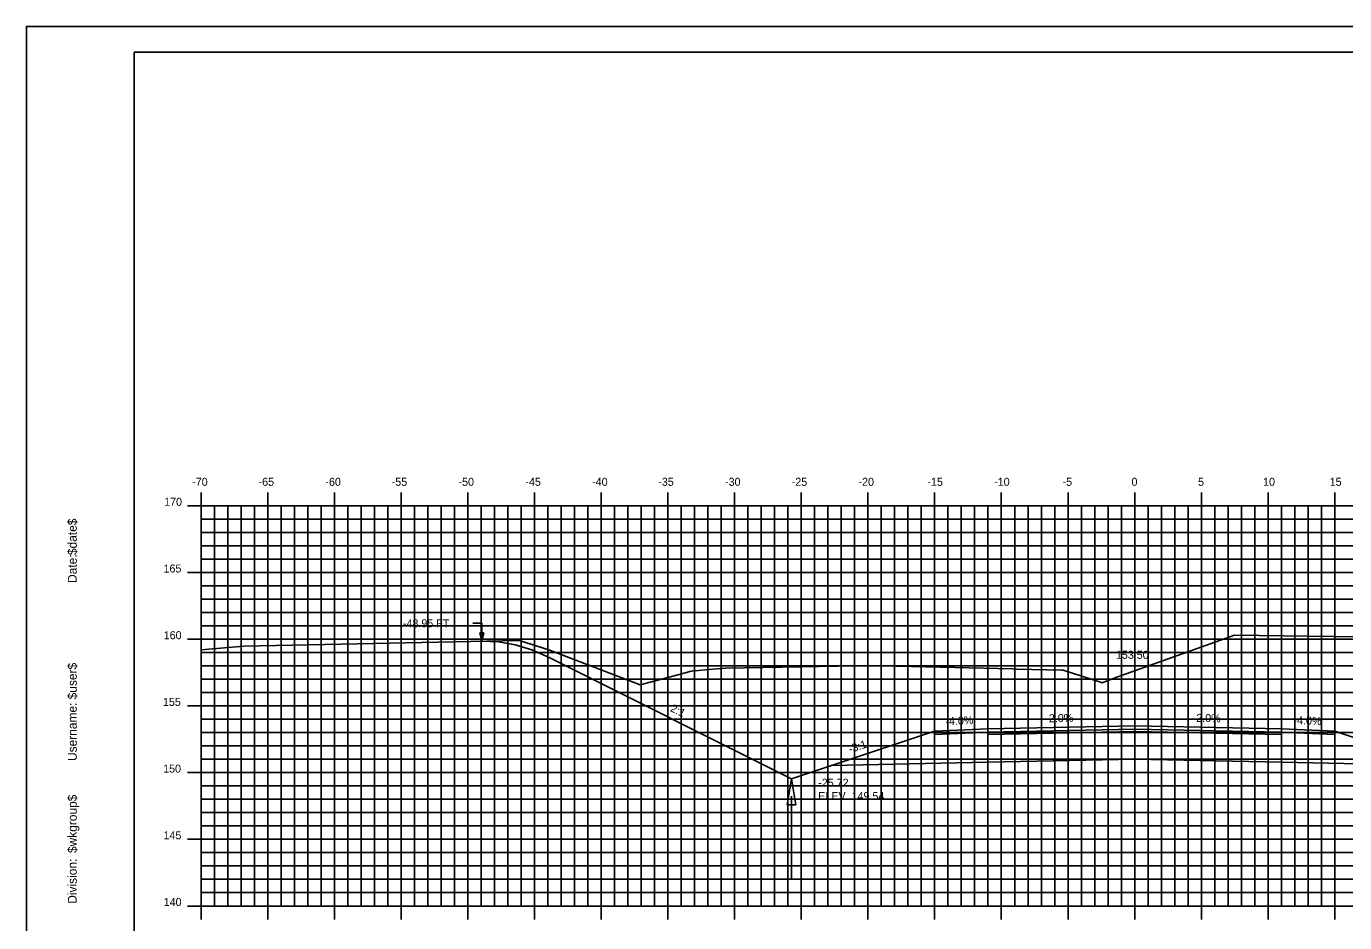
# Model space of a CAD drawing. Extents: x 1143420 to 1143590, y 608981 to 609091.
# Drawn here: x 1143420 to 1143518.8, y 609024.1 to 609091.3 of the extents above; entities that cross this region are included whole.
import ezdxf

# ---------------------------------------------------------------- set-up
doc = ezdxf.new("R2010")
doc.units = 0
for name, color, linetype in [('ANNOTATION', 7, 'Continuous'), ('BORDER', 7, 'Continuous'), ('D_Drainage_Ditch_Line', 7, 'Continuous'), ('D_Roadway_Centerline', 7, 'Continuous'), ('D_Roadway_Centerline_Text', 7, 'Continuous'), ('D_Roadway_Edge_Shoulder', 7, 'Continuous'), ('D_Roadway_Edge_TW', 7, 'Continuous'), ('D_Roadway_Pavement', 7, 'Continuous'), ('D_Roadway_SlopeLines', 7, 'Continuous'), ('D_Roadway_SubGrade', 7, 'Continuous'), ('D_Text_Standard', 7, 'Continuous'), ('H_V ANNOTATION', 7, 'Continuous'), ('MAJOR', 7, 'Continuous'), ('MINOR', 7, 'Continuous'), ('PLOT BOUNDARY', 7, 'Continuous'), ('S_Roadway_Centerline', 7, 'Continuous')]:
    doc.layers.add(name, color=color, linetype=linetype)

msp = doc.modelspace()

# ---------------------------------------------------------------- linework, layer by layer
msp.add_lwpolyline([(1143454.133, 609045.188), (1143455.383, 609045.133), (1143456.633, 609044.915), (1143457.883, 609044.534), (1143459.133, 609043.99), (1143477.355, 609034.879), (1143480.355, 609035.879), (1143488.079, 609038.454), (1143488.08, 609038.454), (1143492.08, 609038.614), (1143503.08, 609038.834), (1143514.08, 609038.614), (1143518.08, 609038.454), (1143525.803, 609035.879), (1143528.803, 609034.879), (1143546.922, 609043.939), (1143548.172, 609044.484), (1143549.422, 609044.87), (1143550.672, 609045.096), (1143551.922, 609045.163)])
at = {"layer": 'BORDER'}
msp.add_lwpolyline([(1143428.08, 608984.335), (1143588.08, 608984.335), (1143588.08, 609089.335), (1143428.08, 609089.335)], close=True, dxfattribs=at)
at = {"layer": 'D_Drainage_Ditch_Line'}
msp.add_line((1143477.355, 609033.567), (1143477.355, 609027.323), dxfattribs=at)
msp.add_lwpolyline([(1143477.683, 609032.911), (1143477.027, 609032.911), (1143477.355, 609034.879)], close=True, dxfattribs=at)
at = {"layer": 'D_Roadway_Edge_Shoulder'}
for points in [[(1143492.08, 609038.614), (1143488.08, 609038.454), (1143488.08, 609038.204), (1143492.08, 609038.364)], [(1143514.08, 609038.614), (1143518.08, 609038.454), (1143518.08, 609038.204), (1143514.08, 609038.364)]]:
    msp.add_lwpolyline(points, close=True, dxfattribs=at)
at = {"layer": 'D_Roadway_Edge_TW'}
msp.add_lwpolyline([(1143492.08, 609038.364), (1143492.08, 609038.614), (1143503.08, 609038.834), (1143514.08, 609038.614), (1143514.08, 609038.364), (1143503.08, 609038.584)], close=True, dxfattribs=at)
at = {"layer": 'D_Roadway_Pavement'}
msp.add_lwpolyline([(1143492.08, 609038.197), (1143492.08, 609038.364), (1143503.08, 609038.584), (1143514.08, 609038.364), (1143514.08, 609038.197), (1143503.08, 609038.417)], close=True, dxfattribs=at)
at = {"layer": 'D_Roadway_SlopeLines'}
for points in [[(1143477.355, 609034.879), (1143459.133, 609043.99), (1143457.883, 609044.534), (1143456.633, 609044.915), (1143455.383, 609045.133), (1143454.133, 609045.188)], [(1143480.355, 609035.879), (1143477.355, 609034.879)]]:
    msp.add_lwpolyline(points, dxfattribs=at)
at = {"layer": 'D_Roadway_SubGrade'}
for points in [[(1143492.08, 609038.197), (1143492.08, 609038.364), (1143488.08, 609038.204), (1143488.08, 609038.454), (1143488.079, 609038.454), (1143480.355, 609035.879), (1143492.08, 609036.114)], [(1143492.08, 609036.114), (1143492.08, 609038.197), (1143503.08, 609038.417), (1143514.08, 609038.197), (1143514.08, 609036.114), (1143503.08, 609036.334)], [(1143514.08, 609038.197), (1143514.08, 609038.364), (1143518.08, 609038.204), (1143518.08, 609038.454), (1143518.08, 609038.454), (1143525.803, 609035.879), (1143514.08, 609036.114)]]:
    msp.add_lwpolyline(points, close=True, dxfattribs=at)
at = {"layer": 'D_Text_Standard'}
msp.add_lwpolyline([(1143454.133, 609045.24), (1143454.129, 609046.527), (1143453.449, 609046.527)], dxfattribs=at)
msp.add_lwpolyline([(1143454.133, 609045.24), (1143453.986, 609045.822), (1143454.277, 609045.823)], close=True, dxfattribs=at)
at = {"layer": 'MAJOR'}
for p, q in [((1143433.08, 609056.337), (1143433.08, 609055.335)), ((1143438.08, 609056.337), (1143438.08, 609055.335)), ((1143443.08, 609056.337), (1143443.08, 609055.335)), ((1143448.08, 609056.337), (1143448.08, 609055.335)), ((1143453.08, 609056.337), (1143453.08, 609055.335)), ((1143458.08, 609056.337), (1143458.08, 609055.335)), ((1143463.08, 609056.337), (1143463.08, 609055.335)), ((1143468.08, 609056.337), (1143468.08, 609055.335)), ((1143473.08, 609056.337), (1143473.08, 609055.335)), ((1143478.08, 609056.337), (1143478.08, 609055.335)), ((1143483.08, 609056.337), (1143483.08, 609055.335)), ((1143488.08, 609056.337), (1143488.08, 609055.335)), ((1143493.08, 609056.337), (1143493.08, 609055.335)), ((1143498.08, 609056.337), (1143498.08, 609055.335)), ((1143503.08, 609056.337), (1143503.08, 609055.335)), ((1143508.08, 609056.337), (1143508.08, 609055.335)), ((1143513.08, 609056.337), (1143513.08, 609055.335)), ((1143518.08, 609056.337), (1143518.08, 609055.335)), ((1143432.078, 609055.335), (1143433.08, 609055.335)), ((1143433.08, 609055.335), (1143573.08, 609055.335)), ((1143433.08, 609025.335), (1143433.08, 609055.335)), ((1143433.08, 609025.335), (1143433.08, 609055.335)), ((1143433.08, 609055.335), (1143573.08, 609055.335)), ((1143438.08, 609025.335), (1143438.08, 609055.335)), ((1143443.08, 609025.335), (1143443.08, 609055.335)), ((1143448.08, 609025.335), (1143448.08, 609055.335)), ((1143453.08, 609025.335), (1143453.08, 609055.335)), ((1143458.08, 609025.335), (1143458.08, 609055.335)), ((1143463.08, 609025.335), (1143463.08, 609055.335)), ((1143468.08, 609025.335), (1143468.08, 609055.335)), ((1143473.08, 609025.335), (1143473.08, 609055.335)), ((1143478.08, 609025.335), (1143478.08, 609055.335)), ((1143483.08, 609025.335), (1143483.08, 609055.335)), ((1143488.08, 609025.335), (1143488.08, 609055.335)), ((1143493.08, 609025.335), (1143493.08, 609055.335)), ((1143498.08, 609025.335), (1143498.08, 609055.335)), ((1143503.08, 609025.335), (1143503.08, 609055.335)), ((1143508.08, 609025.335), (1143508.08, 609055.335)), ((1143513.08, 609025.335), (1143513.08, 609055.335)), ((1143518.08, 609025.335), (1143518.08, 609055.335)), ((1143432.078, 609050.335), (1143433.08, 609050.335)), ((1143433.08, 609050.335), (1143573.08, 609050.335)), ((1143432.078, 609045.335), (1143433.08, 609045.335)), ((1143433.08, 609045.335), (1143573.08, 609045.335)), ((1143432.078, 609040.335), (1143433.08, 609040.335)), ((1143433.08, 609040.335), (1143573.08, 609040.335)), ((1143432.078, 609035.335), (1143433.08, 609035.335)), ((1143433.08, 609035.335), (1143573.08, 609035.335)), ((1143432.078, 609030.335), (1143433.08, 609030.335)), ((1143433.08, 609030.335), (1143573.08, 609030.335)), ((1143432.078, 609025.335), (1143433.08, 609025.335)), ((1143433.08, 609025.335), (1143573.08, 609025.335)), ((1143433.08, 609025.335), (1143573.08, 609025.335)), ((1143433.08, 609024.333), (1143433.08, 609025.335)), ((1143438.08, 609024.333), (1143438.08, 609025.335)), ((1143443.08, 609024.333), (1143443.08, 609025.335)), ((1143448.08, 609024.333), (1143448.08, 609025.335)), ((1143453.08, 609024.333), (1143453.08, 609025.335)), ((1143458.08, 609024.333), (1143458.08, 609025.335)), ((1143463.08, 609024.333), (1143463.08, 609025.335)), ((1143468.08, 609024.333), (1143468.08, 609025.335)), ((1143473.08, 609024.333), (1143473.08, 609025.335)), ((1143478.08, 609024.333), (1143478.08, 609025.335)), ((1143483.08, 609024.333), (1143483.08, 609025.335)), ((1143488.08, 609024.333), (1143488.08, 609025.335)), ((1143493.08, 609024.333), (1143493.08, 609025.335)), ((1143498.08, 609024.333), (1143498.08, 609025.335)), ((1143503.08, 609024.333), (1143503.08, 609025.335)), ((1143508.08, 609024.333), (1143508.08, 609025.335)), ((1143513.08, 609024.333), (1143513.08, 609025.335)), ((1143518.08, 609024.333), (1143518.08, 609025.335))]:
    msp.add_line(p, q, dxfattribs=at)
at = {"layer": 'MINOR'}
for p, q in [((1143434.08, 609025.335), (1143434.08, 609055.335)), ((1143435.08, 609025.335), (1143435.08, 609055.335)), ((1143436.08, 609025.335), (1143436.08, 609055.335)), ((1143437.08, 609025.335), (1143437.08, 609055.335)), ((1143439.08, 609025.335), (1143439.08, 609055.335)), ((1143440.08, 609025.335), (1143440.08, 609055.335)), ((1143441.08, 609025.335), (1143441.08, 609055.335)), ((1143442.08, 609025.335), (1143442.08, 609055.335)), ((1143444.08, 609025.335), (1143444.08, 609055.335)), ((1143445.08, 609025.335), (1143445.08, 609055.335)), ((1143446.08, 609025.335), (1143446.08, 609055.335)), ((1143447.08, 609025.335), (1143447.08, 609055.335)), ((1143449.08, 609025.335), (1143449.08, 609055.335)), ((1143450.08, 609025.335), (1143450.08, 609055.335)), ((1143451.08, 609025.335), (1143451.08, 609055.335)), ((1143452.08, 609025.335), (1143452.08, 609055.335)), ((1143454.08, 609025.335), (1143454.08, 609055.335)), ((1143455.08, 609025.335), (1143455.08, 609055.335)), ((1143456.08, 609025.335), (1143456.08, 609055.335)), ((1143457.08, 609025.335), (1143457.08, 609055.335)), ((1143459.08, 609025.335), (1143459.08, 609055.335)), ((1143460.08, 609025.335), (1143460.08, 609055.335)), ((1143461.08, 609025.335), (1143461.08, 609055.335)), ((1143462.08, 609025.335), (1143462.08, 609055.335)), ((1143464.08, 609025.335), (1143464.08, 609055.335)), ((1143465.08, 609025.335), (1143465.08, 609055.335)), ((1143466.08, 609025.335), (1143466.08, 609055.335)), ((1143467.08, 609025.335), (1143467.08, 609055.335)), ((1143469.08, 609025.335), (1143469.08, 609055.335)), ((1143470.08, 609025.335), (1143470.08, 609055.335)), ((1143471.08, 609025.335), (1143471.08, 609055.335)), ((1143472.08, 609025.335), (1143472.08, 609055.335)), ((1143474.08, 609025.335), (1143474.08, 609055.335)), ((1143475.08, 609025.335), (1143475.08, 609055.335)), ((1143476.08, 609025.335), (1143476.08, 609055.335)), ((1143477.08, 609025.335), (1143477.08, 609055.335)), ((1143479.08, 609025.335), (1143479.08, 609055.335)), ((1143480.08, 609025.335), (1143480.08, 609055.335)), ((1143481.08, 609025.335), (1143481.08, 609055.335)), ((1143482.08, 609025.335), (1143482.08, 609055.335)), ((1143484.08, 609025.335), (1143484.08, 609055.335)), ((1143485.08, 609025.335), (1143485.08, 609055.335)), ((1143486.08, 609025.335), (1143486.08, 609055.335)), ((1143487.08, 609025.335), (1143487.08, 609055.335)), ((1143489.08, 609025.335), (1143489.08, 609055.335)), ((1143490.08, 609025.335), (1143490.08, 609055.335)), ((1143491.08, 609025.335), (1143491.08, 609055.335)), ((1143492.08, 609025.335), (1143492.08, 609055.335)), ((1143494.08, 609025.335), (1143494.08, 609055.335)), ((1143495.08, 609025.335), (1143495.08, 609055.335)), ((1143496.08, 609025.335), (1143496.08, 609055.335)), ((1143497.08, 609025.335), (1143497.08, 609055.335)), ((1143499.08, 609025.335), (1143499.08, 609055.335)), ((1143500.08, 609025.335), (1143500.08, 609055.335)), ((1143501.08, 609025.335), (1143501.08, 609055.335)), ((1143502.08, 609025.335), (1143502.08, 609055.335)), ((1143504.08, 609025.335), (1143504.08, 609055.335)), ((1143505.08, 609025.335), (1143505.08, 609055.335)), ((1143506.08, 609025.335), (1143506.08, 609055.335)), ((1143507.08, 609025.335), (1143507.08, 609055.335)), ((1143509.08, 609025.335), (1143509.08, 609055.335)), ((1143510.08, 609025.335), (1143510.08, 609055.335)), ((1143511.08, 609025.335), (1143511.08, 609055.335)), ((1143512.08, 609025.335), (1143512.08, 609055.335)), ((1143514.08, 609025.335), (1143514.08, 609055.335)), ((1143515.08, 609025.335), (1143515.08, 609055.335)), ((1143516.08, 609025.335), (1143516.08, 609055.335)), ((1143517.08, 609025.335), (1143517.08, 609055.335)), ((1143433.08, 609054.335), (1143573.08, 609054.335)), ((1143433.08, 609054.335), (1143434.082, 609054.335)), ((1143433.08, 609053.335), (1143573.08, 609053.335)), ((1143433.08, 609053.335), (1143434.082, 609053.335)), ((1143433.08, 609052.335), (1143573.08, 609052.335)), ((1143433.08, 609052.335), (1143434.082, 609052.335)), ((1143433.08, 609051.335), (1143573.08, 609051.335)), ((1143433.08, 609051.335), (1143434.082, 609051.335)), ((1143433.08, 609049.335), (1143573.08, 609049.335)), ((1143433.08, 609049.335), (1143434.082, 609049.335)), ((1143433.08, 609048.335), (1143573.08, 609048.335)), ((1143433.08, 609048.335), (1143434.082, 609048.335)), ((1143433.08, 609047.335), (1143573.08, 609047.335)), ((1143433.08, 609047.335), (1143434.082, 609047.335)), ((1143433.08, 609046.335), (1143573.08, 609046.335)), ((1143433.08, 609046.335), (1143434.082, 609046.335)), ((1143433.08, 609044.335), (1143573.08, 609044.335)), ((1143433.08, 609044.335), (1143434.082, 609044.335)), ((1143433.08, 609043.335), (1143573.08, 609043.335)), ((1143433.08, 609043.335), (1143434.082, 609043.335)), ((1143433.08, 609042.335), (1143573.08, 609042.335)), ((1143433.08, 609042.335), (1143434.082, 609042.335)), ((1143433.08, 609041.335), (1143573.08, 609041.335)), ((1143433.08, 609041.335), (1143434.082, 609041.335)), ((1143433.08, 609039.335), (1143573.08, 609039.335)), ((1143433.08, 609039.335), (1143434.082, 609039.335)), ((1143433.08, 609038.335), (1143573.08, 609038.335)), ((1143433.08, 609038.335), (1143434.082, 609038.335)), ((1143433.08, 609037.335), (1143573.08, 609037.335)), ((1143433.08, 609037.335), (1143434.082, 609037.335)), ((1143433.08, 609036.335), (1143573.08, 609036.335)), ((1143433.08, 609036.335), (1143434.082, 609036.335)), ((1143433.08, 609034.335), (1143573.08, 609034.335)), ((1143433.08, 609034.335), (1143434.082, 609034.335)), ((1143433.08, 609033.335), (1143573.08, 609033.335)), ((1143433.08, 609033.335), (1143434.082, 609033.335)), ((1143433.08, 609032.335), (1143573.08, 609032.335)), ((1143433.08, 609032.335), (1143434.082, 609032.335)), ((1143433.08, 609031.335), (1143573.08, 609031.335)), ((1143433.08, 609031.335), (1143434.082, 609031.335)), ((1143433.08, 609029.335), (1143573.08, 609029.335)), ((1143433.08, 609029.335), (1143434.082, 609029.335)), ((1143433.08, 609028.335), (1143573.08, 609028.335)), ((1143433.08, 609028.335), (1143434.082, 609028.335)), ((1143433.08, 609027.335), (1143573.08, 609027.335)), ((1143433.08, 609027.335), (1143434.082, 609027.335)), ((1143433.08, 609026.335), (1143573.08, 609026.335)), ((1143433.08, 609026.335), (1143434.082, 609026.335))]:
    msp.add_line(p, q, dxfattribs=at)
at = {"layer": 'PLOT BOUNDARY'}
msp.add_lwpolyline([(1143419.986, 608981.276), (1143589.986, 608981.276), (1143589.986, 609091.276), (1143419.986, 609091.276)], close=True, dxfattribs=at)
at = {"layer": 'S_Roadway_Centerline'}
msp.add_lwpolyline([(1143433.08, 609044.546), (1143436.28, 609044.822), (1143439.921, 609044.888), (1143456.939, 609045.247), (1143459.16, 609044.533), (1143466.012, 609041.915), (1143468.915, 609042.679), (1143469.816, 609042.947), (1143471.462, 609043.097), (1143472.407, 609043.168), (1143482.258, 609043.346), (1143483.051, 609043.354), (1143493.938, 609043.106), (1143494.247, 609043.095), (1143497.626, 609043.011), (1143497.719, 609043.007), (1143500.594, 609042.08), (1143500.644, 609042.068), (1143501.744, 609042.494), (1143510.556, 609045.639), (1143534.693, 609045.32), (1143538.189, 609045.275), (1143546.024, 609045.224), (1143573.08, 609044.943)], dxfattribs=at)

# ---------------------------------------------------------------- texts
at = {"layer": 'ANNOTATION'}
for s, rotation, p in [('2:1', 333.43495, (1143468.211, 609039.969)), ('-4.0%', 2.29061, (1143488.896, 609038.887)), ('-2.0%', 1.14576, (1143496.383, 609039.1)), ('-2.0%', 358.85424, (1143507.423, 609039.147)), ('-4.0%', 357.70939, (1143514.975, 609038.979)), ('-3:1', 18.43482, (1143481.734, 609036.793))]:
    msp.add_text(s, height=0.6, rotation=rotation, dxfattribs=at).set_placement(p)
at = {"layer": 'BORDER'}
for s, p in [('$date$', (1143423.765, 609051.64)), ('Date:', (1143423.765, 609049.552)), ('$user$', (1143423.765, 609040.827)), ('Username:', (1143423.765, 609036.203)), ('$wkgroup$', (1143423.765, 609029.305)), ('Division:', (1143423.765, 609025.501))]:
    msp.add_text(s, height=0.6696, rotation=90, dxfattribs=at).set_placement(p)
at = {"layer": 'D_Roadway_Centerline'}
for s, p in [('C', (1143503.074, 609038.834)), ('L', (1143503.08, 609038.826))]:
    msp.add_text(s, height=0.0146, dxfattribs=at).set_placement(p)
at = {"layer": 'D_Roadway_Centerline_Text'}
msp.add_text('153.50', height=0.6, dxfattribs=at).set_placement((1143501.672, 609043.866))
at = {"layer": 'D_Text_Standard'}
for s, p in [('-48.95 FT', (1143448.22, 609046.227)), ('-25.72', (1143479.355, 609034.279)), ('ELEV. 149.54', (1143479.355, 609033.277))]:
    msp.add_text(s, height=0.6, dxfattribs=at).set_placement(p)
at = {"layer": 'H_V ANNOTATION'}
for s, p in [('-70', (1143432.421, 609056.835)), ('-65', (1143437.397, 609056.835)), ('-60', (1143442.405, 609056.835)), ('-55', (1143447.376, 609056.835)), ('-50', (1143452.384, 609056.835)), ('-45', (1143457.397, 609056.835)), ('-40', (1143462.405, 609056.835)), ('-35', (1143467.36, 609056.835)), ('-30', (1143472.368, 609056.835)), ('-25', (1143477.365, 609056.835)), ('-20', (1143482.373, 609056.835)), ('-15', (1143487.536, 609056.835)), ('-10', (1143492.544, 609056.835)), ('-5', (1143497.67, 609056.835)), ('0', (1143502.839, 609056.835)), ('5', (1143507.831, 609056.835)), ('10', (1143512.705, 609056.835)), ('15', (1143517.697, 609056.835)), ('170', (1143430.316, 609055.335)), ('165', (1143430.268, 609050.335)), ('160', (1143430.284, 609045.335)), ('155', (1143430.225, 609040.335)), ('150', (1143430.241, 609035.335)), ('145', (1143430.268, 609030.335)), ('140', (1143430.284, 609025.335))]:
    msp.add_text(s, height=0.6, dxfattribs=at).set_placement(p)
at = {"layer": 'MAJOR'}
msp.add_text('-', height=0.006, dxfattribs=at).set_placement((1143433.075, 609025.335))
at = {"layer": 'S_Roadway_Centerline'}
for s, p in [('L', (1143483.042, 609043.347)), ('C', (1143483.045, 609043.354))]:
    msp.add_text(s, height=0.0146, dxfattribs=at).set_placement(p)

doc.saveas('drawing.dxf')
